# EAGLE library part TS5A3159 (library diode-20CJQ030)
Ti's TS5A3159 1 Ohm single-pole double-throw (SPDT) analog switch Description: The TS5A3159 is a single-pole double-throw (SPDT) analog switch that is designed to operate from 1.65 V to 5.5 V. The device offers a low ON-state resistance and an excellent ON-resistance, matching with the break-before-make feature to prevent signal distortion during the transferring of a signal from one channel to another. The device has an excellent total harmonic distortion (THD) performance and consumes very low power. These features make this device suitable for portable audio applications. Features: Specified Break-Before-Make Switching Low ON-State Resistance (1 ) Control Inputs Are 5-V Tolerant Low Charge Injection Excellent ON-Resistance Matching Low Total Harmonic Distortion 1.65-V to 5.5-V Single-Supply Operation Latch-Up Performance Exceeds 100 mA Per JESD 78, Class II ESD Performance Tested Per JESD 22 - 2000-V Human-Body Model (A114-B, Class II) - 1000-V Charged-Device Model (C101) Applications: Cell Phones PDAs Portable Instrumentation Please send any comments to: messi@users.sourceforge.net
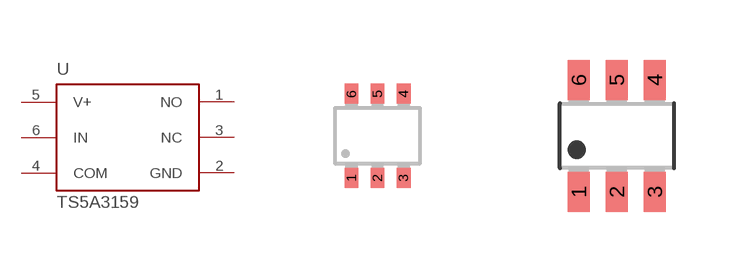
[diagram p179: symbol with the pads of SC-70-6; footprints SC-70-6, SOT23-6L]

Designator prefix U

## TS5A3159-DCK  [SC-70-6]
1  NO
2  GND  pwr
3  NC
4  COM
5  V+  pwr
6  IN  in

## TS5A3159-DBV  [SOT23-6L]
Pads as for SC-70-6

## Footprint SC-70-6 (pad centres in mm)
Texas Instruments Package SC-70-6 (-DCK)
smd 0.35 x 0.5: 1 -0.65,-1.05; 2 0,-1.05; 3 0.65,-1.05; 4 0.65,1.05; 5 0,1.05; 6 -0.65,1.05

## Footprint SOT23-6L (pad centres in mm)
Small Outline Transistor
smd 0.55 x 1: 1 -0.95,-1.4; 2 0,-1.4; 3 0.95,-1.4; 4 0.95,1.4; 5 0,1.4; 6 -0.95,1.4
